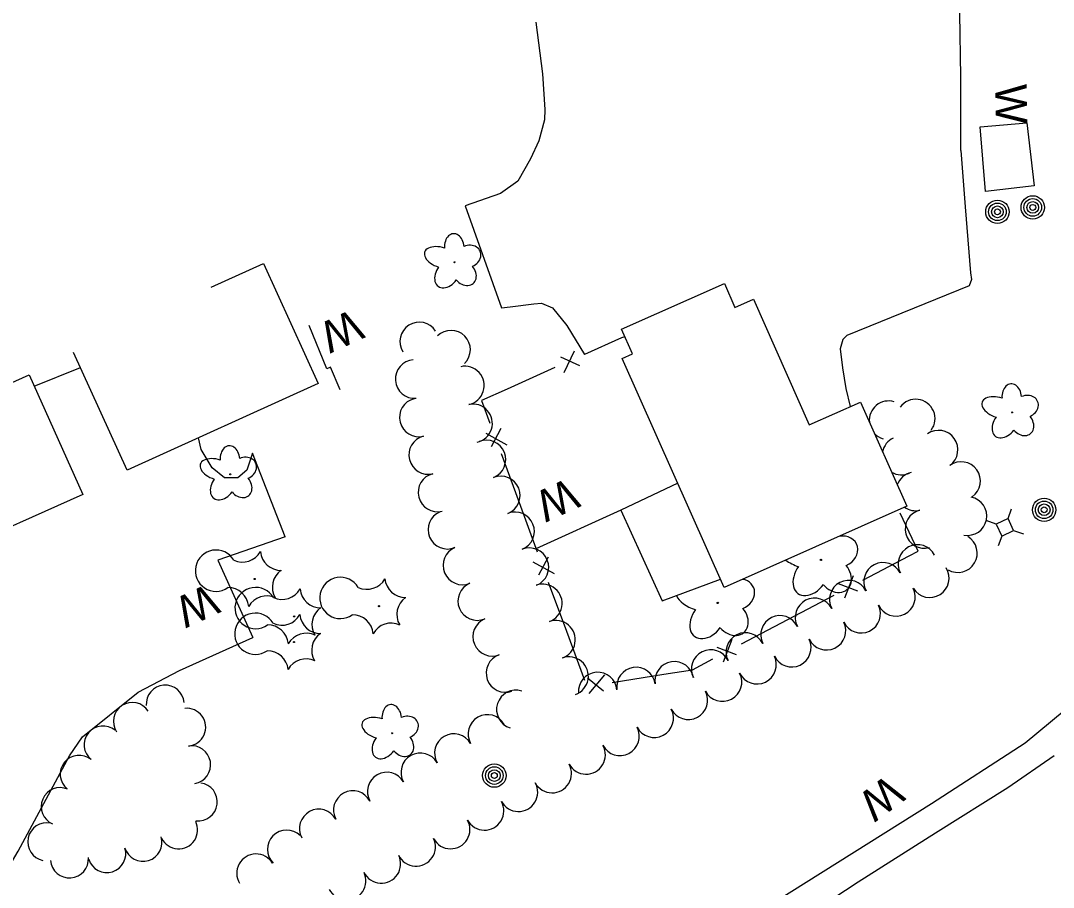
# Model space of a CAD drawing. Extents: x 588843 to 2552415, y 180129 to 269402.
# Drawn here: x 593585 to 593781.7, y 188224.6 to 188389.7 of the extents above; entities that cross this region are included whole.
import ezdxf

# ---------------------------------------------------------------- set-up
doc = ezdxf.new("R2010")
doc.units = 0
for name, color, linetype in [('Default', 7, 'Continuous'), ('E_BLD', 7, 'Continuous'), ('E_BLD_HvyDash', 7, 'Continuous'), ('E_DWY', 7, 'Continuous'), ('E_FEN_P', 7, 'Continuous'), ('E_LAND_TreeLine_P', 7, 'Continuous'), ('E_LAND_Vegetation', 7, 'Continuous'), ('E_MISCPROP', 7, 'Continuous'), ('E_RDWY', 7, 'Continuous'), ('E_RDWY_Gravel', 7, 'Continuous'), ('E_UTL_AG_Bold', 7, 'Continuous'), ('E_WAL', 7, 'Continuous'), ('E_WAL_Text', 7, 'Continuous')]:
    doc.layers.add(name, color=color, linetype=linetype)

# ---------------------------------------------------------------- blocks, each defined once
blk = doc.blocks.new('PED')
at = {"layer": 'Default'}
for p, q in [((-2.5, 2.5), (-5.33, 5.33)), ((2.5, 2.5), (5.33, 5.33)), ((-2.5, -2.5), (-5.33, -5.33)), ((2.5, -2.5), (5.33, -5.33))]:
    blk.add_line(p, q, dxfattribs=at)
blk.add_lwpolyline([(-2.5, -2.5), (2.5, -2.5), (2.5, 2.5), (-2.5, 2.5)], close=True, dxfattribs=at)
blk = doc.blocks.new('POLE')
at = {"layer": 'Default'}
for radius in [4.46, 3.35, 2.23, 1.12]:
    blk.add_circle((0, 0), radius, dxfattribs=at)
blk = doc.blocks.new('W_23')
at = {"layer": 'E_WAL_Text'}
blk.add_text('W', height=12, dxfattribs=at).set_placement((-4.46, -6))
blk = doc.blocks.new('W_24')
at = {"layer": 'E_WAL_Text'}
blk.add_text('W', height=12, dxfattribs=at).set_placement((-4.46, -6))
blk = doc.blocks.new('DTRE')
at = {"layer": 'Default'}
blk.add_circle((-0.18, 0), 0.183, dxfattribs=at)
for centre, major_axis, ratio in [((-1.87, 5.32), (1.36, -4.98), 0.782863), ((4.06, 2.74), (-5.27, -2.93), 0.691916), ((-5.87, 0.15), (4.93, -0.12), 0.832022), ((3.54, -3.71), (-5.01, 4.58), 0.560249), ((-2.49, -5.24), (1.8, 4.86), 0.716896)]:
    blk.add_ellipse(centre, major_axis=major_axis, ratio=ratio, start_param=1.570796, end_param=4.712389, dxfattribs=at)
blk = doc.blocks.new('CTRE')
at = {"layer": 'Default'}
blk.add_circle((0, 0), 0.223, dxfattribs=at)
for centre, start, end in [((-11.97, 8.96), 280.2067, 5.9716), ((1.81, 14.92), 220.2113, 305.9762), ((13.83, 5.89), 160.2113, 245.9762), ((-13.83, -5.9), 340.2113, 65.9762), ((12.03, -9.04), 185.9272, 100.2511), ((-1.81, -14.93), 40.2113, 125.9762)]:
    blk.add_arc(centre, 7.87, start, end, dxfattribs=at)
blk = doc.blocks.new('W_27')
at = {"layer": 'E_WAL_Text'}
blk.add_text('W', height=12, dxfattribs=at).set_placement((-4.46, -6))
blk = doc.blocks.new('U298')
at = {"layer": 'E_LAND_Vegetation'}
blk.add_circle((0.09, 0.03), 0.128, dxfattribs=at)
for centre, major_axis, ratio, start_param, end_param in [((3.75, 1.6), (-3.17, -1.37), 0.832022, 1.570796, 4.433022), ((-3.37, 1.29), (4.53, -1.44), 0.560249, 4.111817, 4.712389), ((-1.81, -2.95), (2.49, 3.41), 0.691916, 1.570796, 4.712389), ((2.72, -2.86), (-2.33, 2.77), 0.782863, 1.570796, 4.712389)]:
    blk.add_ellipse(centre, major_axis=major_axis, ratio=ratio, start_param=start_param, end_param=end_param, dxfattribs=at)

msp = doc.modelspace()

# ---------------------------------------------------------------- linework, layer by layer
at = {"layer": 'E_BLD'}
msp.add_lwpolyline([(593621.29, 188338.9), (593631.23, 188343.41), (593641.62, 188320.53), (593605.25, 188304), (593595.05, 188326.47)], dxfattribs=at)
for points in [[(593724.53, 188336.6), (593735.17, 188312.67), (593744.91, 188317), (593753.74, 188297.16), (593718.98, 188281.69), (593699.57, 188325.32), (593701.49, 188326.18), (593699.39, 188330.89), (593719, 188339.61), (593721.03, 188335.04), (593724.53, 188336.6)], [(593561.83, 188311.1), (593586.61, 188322.2), (593596.81, 188299.42), (593572.04, 188288.32), (593561.83, 188311.1)]]:
    msp.add_lwpolyline(points, close=True, dxfattribs=at)
at = {"layer": 'E_BLD_HvyDash'}
msp.add_lwpolyline([(593710.14, 188301.57), (593699.27, 188296.42), (593707.19, 188279.14), (593718.28, 188283.28)], dxfattribs=at)
at = {"layer": 'E_DWY'}
for points in [[(593764.07, 188364.94), (593764.07, 188378.97), (593763.83, 188391), (593763.04, 188399.28), (593759.94, 188404.55), (593757.36, 188412.22), (593755.89, 188417.04), (593754.97, 188421.78), (593754.11, 188435.35), (593753.88, 188443.08), (593753.75, 188451.7), (593753.06, 188460.33), (593752.81, 188462.25)], [(593683.11, 188389.39), (593684.39, 188379.56), (593684.82, 188372.77), (593684.77, 188370.75), (593683.64, 188366.79), (593682.08, 188363.36), (593679.66, 188359.11), (593676.36, 188356.76), (593669.61, 188354.41), (593676.57, 188334.95), (593678.19, 188335.13), (593682.73, 188335.75), (593684.19, 188335.84), (593686.26, 188334.98), (593689.02, 188331.61), (593692.36, 188326.08)], [(593764.07, 188364.94), (593764.88, 188354.23), (593765.86, 188341.64), (593766.06, 188340.38), (593765.62, 188339.18), (593742.3, 188329.68), (593741.58, 188328.94), (593741.05, 188327.17), (593741.48, 188323.5), (593742.13, 188319.61), (593742.96, 188316.14)], [(593587.59, 188320.01), (593596.36, 188323.58)], [(593635.35, 188291.34), (593629.12, 188307.24), (593628.08, 188304.02), (593626.35, 188302.55), (593623.8, 188302.55), (593621.47, 188304.46), (593619.39, 188307.95), (593618.86, 188310.18)], [(593539.8, 188134.18), (593535.15, 188137.59), (593532.54, 188139.85), (593531.46, 188141.45), (593530.53, 188143.73), (593530.3, 188146.14), (593530.39, 188149.61), (593531.59, 188155.73), (593533.85, 188163.21), (593535.47, 188166.5), (593537.46, 188169.6), (593562.1, 188198.46), (593569.6, 188207.86), (593577.78, 188220.1), (593584.5, 188231.42), (593594.27, 188249.63), (593596.74, 188253.25), (593607.35, 188261.74), (593615.26, 188265.86), (593629.22, 188272.13)]]:
    msp.add_lwpolyline(points, dxfattribs=at)
at = {"layer": 'E_FEN_P'}
for p, q in [((593691.48, 188323.9), (593687.89, 188325.54)), ((593690.39, 188326.73), (593688.46, 188322.55)), ((593676.45, 188311.96), (593674.58, 188308.49)), ((593673.56, 188311.06), (593677.6, 188308.85)), ((593682.56, 188286.58), (593686.59, 188284.37)), ((593685.45, 188287.48), (593683.58, 188284.01)), ((593741.92, 188279.69), (593743.58, 188283.97)), ((593740.65, 188282.43), (593744.34, 188281.03)), ((593717.57, 188270.29), (593721.26, 188268.89)), ((593718.83, 188267.54), (593720.5, 188271.83)), ((593692.94, 188264.49), (593695.98, 188261.98)), ((593693.25, 188261.48), (593696.21, 188265.01))]:
    msp.add_line(p, q, dxfattribs=at)
for points in [[(593700.04, 188329.43), (593699.43, 188329.24), (593692.36, 188326.08)], [(593686.73, 188323.56), (593677.64, 188319.49)], [(593677.64, 188319.49), (593672.76, 188317.31), (593674.34, 188312.98)], [(593676.47, 188307.2), (593679.91, 188297.85)], [(593679.91, 188297.85), (593683.34, 188288.5)], [(593754.18, 188287.71), (593755.91, 188288.63), (593752.51, 188295.87)], [(593745.37, 188283.08), (593754.18, 188287.71)], [(593685.47, 188282.72), (593688.91, 188273.37)], [(593731.1, 188275.57), (593739.91, 188280.21)], [(593722.28, 188270.93), (593731.1, 188275.57)], [(593688.91, 188273.37), (593692.34, 188264.02)], [(593707.45, 188265.14), (593712.92, 188266.01), (593716.83, 188268.06)], [(593697.61, 188263.58), (593707.45, 188265.14)]]:
    msp.add_lwpolyline(points, dxfattribs=at)
at = {"layer": 'E_LAND_TreeLine_P'}
for centre, radius, start, end in [((593660.9, 188328.56), 3.68, 32.3888, 212.3888), ((593666.95, 188326.99), 3.68, 314.7867, 134.7867), ((593660.03, 188321.39), 3.68, 94.4145, 274.4145), ((593669.58, 188320.15), 3.68, 282.2878, 102.2878), ((593660.81, 188314.08), 3.68, 103.993, 283.993), ((593755.45, 188313.86), 3.68, 323.2097, 143.2097), ((593671.14, 188312.95), 3.68, 282.2878, 102.2878), ((593750.29, 188313.54), 3.68, 73.4436, 186.0058), ((593759.8, 188307.94), 3.68, 305.5239, 125.5239), ((593662.59, 188306.93), 3.68, 103.993, 283.993), ((593673.69, 188306.06), 3.68, 291.7282, 111.7282), ((593750.29, 188313.54), 3.68, 221.968, 253.4436), ((593752.73, 188306.81), 3.68, 114.9064, 168.4593), ((593764.08, 188301.95), 3.68, 305.5239, 125.5239), ((593752.73, 188306.81), 3.68, 239.5145, 294.9064), ((593755.41, 188299.99), 3.68, 103.0992, 160.6595), ((593664.37, 188299.79), 3.68, 103.993, 283.993), ((593676.42, 188299.22), 3.68, 291.7282, 111.7282), ((593765.3, 188295.28), 3.68, 259.3478, 79.3478), ((593666.27, 188292.69), 3.68, 112.6907, 292.6907), ((593679.14, 188292.38), 3.68, 291.7282, 111.7282), ((593755.41, 188299.99), 3.68, 235.1707, 283.0992), ((593757.12, 188292.83), 3.68, 104.8791, 284.8791), ((593755.79, 188286.14), 3.68, 27.4238, 207.4238), ((593763.49, 188288.22), 3.68, 239.397, 59.397), ((593669.11, 188285.89), 3.68, 112.6907, 292.6907), ((593681.87, 188285.54), 3.68, 291.7282, 111.7282), ((593749.25, 188282.75), 3.68, 27.4238, 207.4238), ((593758.13, 188283.45), 3.68, 212.183, 32.183), ((593671.95, 188279.1), 3.68, 112.6907, 292.6907), ((593684.43, 188278.64), 3.68, 289.8544, 109.8544), ((593742.71, 188279.36), 3.68, 27.4238, 207.4238), ((593751.68, 188279.92), 3.68, 206.067, 26.067), ((593736.18, 188275.97), 3.68, 27.4238, 207.4238), ((593745.06, 188276.69), 3.68, 206.067, 26.067), ((593729.61, 188272.64), 3.68, 26.2082, 206.2082), ((593674.79, 188272.3), 3.68, 112.6907, 292.6907), ((593686.93, 188271.71), 3.68, 289.8544, 109.8544), ((593738.45, 188273.45), 3.68, 206.067, 26.067), ((593723, 188269.39), 3.68, 26.2082, 206.2082), ((593731.83, 188270.21), 3.68, 206.067, 26.067), ((593677.32, 188265.39), 3.68, 109.5704, 289.5704), ((593689.43, 188264.78), 3.68, 289.8544, 109.8544), ((593716.4, 188266.14), 3.68, 26.2082, 206.2082), ((593725.22, 188266.98), 3.68, 206.067, 26.067), ((593702.19, 188262.8), 3.68, 8.5636, 188.5636), ((593709.47, 188263.9), 3.68, 8.5636, 188.5636), ((593694.89, 188261.85), 3.68, 4.7174, 184.7174), ((593718.65, 188263.66), 3.68, 207.8694, 27.8694), ((593612.51, 188259.48), 3.61, 4.6314, 184.6314), ((593679.3, 188258.44), 3.68, 72.3808, 252.3808), ((593712.14, 188260.22), 3.68, 207.8694, 27.8694), ((593606.26, 188256.16), 3.61, 33.3345, 213.3345), ((593616.62, 188255.06), 3.61, 276.2104, 96.2104), ((593705.63, 188256.78), 3.68, 207.8694, 27.8694), ((593673.88, 188253.78), 3.68, 29.7728, 209.7728), ((593600.69, 188251.69), 3.61, 50.7851, 230.7851), ((593699.12, 188253.33), 3.68, 207.8694, 27.8694), ((593667.49, 188250.12), 3.68, 29.7728, 209.7728), ((593617.55, 188247.91), 3.61, 279.5641, 99.5641), ((593692.66, 188249.8), 3.68, 208.8688, 28.8688), ((593596.13, 188246.1), 3.61, 50.7851, 230.7851), ((593661.1, 188246.46), 3.68, 29.7728, 209.7728), ((593654.71, 188242.81), 3.68, 29.7728, 209.7728), ((593686.21, 188246.24), 3.68, 208.8688, 28.8688), ((593592.5, 188239.94), 3.61, 66.5223, 246.5223), ((593618.83, 188240.83), 3.61, 262.7506, 82.7506), ((593648.25, 188239.27), 3.68, 28.4408, 208.4408), ((593679.77, 188242.69), 3.68, 208.8688, 28.8688), ((593673.32, 188239.13), 3.68, 208.8688, 28.8688), ((593641.77, 188235.77), 3.68, 28.4408, 208.4408), ((593589.94, 188233.22), 3.61, 78.0882, 258.0882), ((593615.08, 188235.5), 3.61, 206.1794, 26.1794), ((593666.87, 188235.58), 3.68, 208.8688, 28.8688), ((593635.65, 188231.79), 3.68, 45.6607, 225.6607), ((593608.29, 188233.11), 3.61, 197.1882, 17.1882), ((593660.29, 188232.27), 3.68, 206.1033, 26.1033), ((593601.4, 188230.98), 3.61, 197.1882, 17.1882), ((593629.82, 188227.23), 3.68, 31.1415, 211.1415), ((593594.29, 188229.95), 3.61, 184.119, 4.119), ((593653.68, 188229.03), 3.68, 206.1033, 26.1033), ((593647.07, 188225.79), 3.68, 206.1033, 26.1033)]:
    msp.add_arc(centre, radius, start, end, dxfattribs=at)
at = {"layer": 'E_LAND_Vegetation'}
msp.add_circle((593717.74, 188278.74), 0.128, dxfattribs=at)
for centre, major_axis, ratio, start_param, end_param in [((593721.4, 188280.31), (-3.17, -1.37), 0.832022, 1.570796, 4.051342), ((593714.28, 188280), (4.53, -1.44), 0.560249, 3.609484, 4.712389), ((593715.85, 188275.75), (2.49, 3.41), 0.691916, 1.570796, 4.712389), ((593720.37, 188275.85), (-2.33, 2.77), 0.782863, 1.570796, 4.712389)]:
    msp.add_ellipse(centre, major_axis=major_axis, ratio=ratio, start_param=start_param, end_param=end_param, dxfattribs=at)
at = {"layer": 'E_RDWY'}
msp.add_lwpolyline([(593781.81, 188249.58), (593772.97, 188243.5), (593759.22, 188234.87), (593744.51, 188225.53), (593718.69, 188208.61), (593696.67, 188196.71), (593683.94, 188189.82), (593674.11, 188185.09), (593660.98, 188179.03), (593644.95, 188171.84), (593629.38, 188164.64), (593615.73, 188158.3), (593593.59, 188147.89), (593578.29, 188140.85), (593559.08, 188131.9), (593545.01, 188125.41), (593528.77, 188117.84), (593516.57, 188112.18), (593503.02, 188105.97), (593489.08, 188099.32)], dxfattribs=at)
at = {"layer": 'E_RDWY_Gravel'}
msp.add_lwpolyline([(593806.21, 188371.19), (593805.8, 188325.67), (593806.09, 188301.88), (593802.63, 188287.53), (593796.7, 188274.16), (593790.91, 188265.64), (593783.7, 188258.17), (593776.29, 188252.01), (593758.44, 188240.45), (593728.62, 188221.72), (593720.11, 188216.47), (593691.17, 188203.12), (593680.23, 188197.49)], dxfattribs=at)
at = {"layer": 'E_WAL'}
msp.add_lwpolyline([(593768.72, 188357.12), (593767.73, 188369.41), (593776.6, 188370.21), (593778.03, 188358.21), (593768.72, 188357.12)], close=True, dxfattribs=at)
for points in [[(593645.85, 188319.35), (593644, 188323.66), (593643.31, 188323.34), (593639.91, 188331.61)], [(593699.27, 188296.42), (593683.13, 188289.07)], [(593635.35, 188291.34), (593622.54, 188286.86), (593629.22, 188272.13)]]:
    msp.add_lwpolyline(points, dxfattribs=at)

# ---------------------------------------------------------------- block references
at = {"layer": 'E_LAND_Vegetation', "xscale": 0.5, "yscale": 0.5, "rotation": -155.21508863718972}
for name, p in [('DTRE', (593667.54, 188343.59)), ('DTRE', (593773.71, 188315)), ('DTRE', (593624.82, 188303.2)), ('CTRE', (593629.54, 188283.3)), ('CTRE', (593653.24, 188278.11)), ('CTRE', (593637.09, 188276.18)), ('CTRE', (593637.04, 188271.28)), ('DTRE', (593655.63, 188253.88))]:
    msp.add_blockref(name, p, dxfattribs=at)
at = {"layer": 'E_LAND_Vegetation'}
msp.add_blockref('U298', (593737.31, 188286.9), dxfattribs=at)
at = {"layer": 'E_MISCPROP'}
for p, xscale, yscale, rotation in [((593777.74, 188354.09), 0.49999999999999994, 0.49999999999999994, -154.79394034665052), ((593771.01, 188353.25), 0.5, 0.5, -155.21508863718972), ((593779.91, 188296.48), 0.49999999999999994, 0.49999999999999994, -154.79394034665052), ((593675.2, 188245.85), 0.5, 0.5, -155.21508863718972)]:
    msp.add_blockref('POLE', p, dxfattribs=dict(at, xscale=xscale, yscale=yscale, rotation=rotation))
at = {"layer": 'E_UTL_AG_Bold', "xscale": 0.49999999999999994, "yscale": 0.49999999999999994, "rotation": -154.79394034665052}
msp.add_blockref('PED', (593772.43, 188293.15), dxfattribs=at)
at = {"layer": 'E_WAL_Text'}
for name, p, xscale, yscale, rotation in [('W_23', (593773.61, 188375.35), 0.49999999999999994, 0.4999999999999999, -89.0813825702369), ('W_24', (593647.51, 188331.18), 0.5, 0.5, -155.21508863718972), ('W_24', (593688.61, 188299.01), 0.5, 0.5, -155.21508863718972), ('W_24', (593620.03, 188278.86), 0.5, 0.5, -155.21508863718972), ('W_27', (593750.18, 188242.49), 0.5, 0.49999999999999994, -143.48607765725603)]:
    msp.add_blockref(name, p, dxfattribs=dict(at, xscale=xscale, yscale=yscale, rotation=rotation))

doc.saveas('drawing.dxf')
